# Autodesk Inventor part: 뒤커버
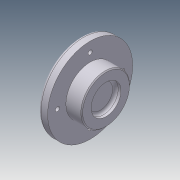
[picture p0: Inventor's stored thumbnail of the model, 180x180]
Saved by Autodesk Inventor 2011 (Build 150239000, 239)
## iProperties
Company: 한국ATC센터
Created: 2014-11
Part Number: 뒤커버
Document SubType Name: Modeling
Designer: KYOUNG IL JANG
Density: 2.71 g/cm^3
Material: 알루미늄-6061
Mass: 280.898 g
Surface Area: 198.677 cm^2
Volume: 103.653 cm^3
Author: KYOUNG IL JANG
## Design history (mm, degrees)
sketch "스케치1"
  geometry: L1 (-13.5, 0)-(13.5, 0); L2 (-13.5, 0)-(-13.5, 45.5); L3 (-13.5, 45.5)-(-3.5, 45.5); L4 (-3.5, 45.5)-(-3.5, 26); L5 (-3.5, 26)-(13.5, 26); L6 (13.5, 26)-(13.5, 0); 2 further points
  constraints: 12 end point, 3 parallel, 2 perpendicular, 1 coincident, 1 horizontal, 1 midpoint
  dimensions: "d0" = 27 distance of L1.start L1.end; "d1" = 91 diameter of L3 L1; "d2" = 52 diameter of L5 L1; "d3" = 10 distance of L2.end L3.end
revolve "회전1" sketch "스케치1" stored, may be unused: angle "d4" = 90 deg
sketch "스케치2"
  geometry: 2 further points
  constraints: 1 vertical alignment
  dimensions: "d14" = 35 distance of point (0, 0) point (0, 35)
hole "구멍2" sketch "스케치2" at (0, 35) diameter "d15" = 4.5; stored, may be unused: countersink angle "d19" = 90 deg, drill point angle "d21" = 118 deg; dims "d16" = 6, "d17" = 8, "d18" = 4.4, "d20" = 8
fillet "모깎기1" dims "d29" = 3
chamfer "모따기2" distance "d30" = 1; stored, may be unused: second distance "d31" = 2, angle "d32" = 30 deg
sketch "스케치3"
  geometry: L1 (-22.444, 6.652)-(-10, 14.967); L2 (-22.444, -6.652)-(-10, -14.967); L3 (10, -14.967)-(22.444, -6.652); L4 (22.444, 6.652)-(10, 14.967); A1 r 18 centre (0, 0) between (-18, 0) and (18, 0); A2 r 8 centre (18, 0) between (22.444, -6.652) and (22.444, 6.652); A3 r 8 centre (-18, 0) between (-22.444, 6.652) and (-22.444, -6.652); 1 further point
  constraints: 10 point on circle, 8 end point, 6 tangent, 3 centre point, 2 horizontal alignment, 2 parallel, 1 coincident, 1 equal radius
  dimensions: "d36" = 36 diameter of A1; "d37" = 16 diameter of A2
extrude "돌출1" join sketch "스케치3" distance "d38" = 7; taper "d39" = 0 deg
hole "구멍3" diameter "d43" = 32; stored, may be unused: countersink angle "d47" = 90 deg, drill point angle "d49" = 0 deg; dims "d41" = 10, "d42" = 10, "d44" = 6, "d45" = 4, "d46" = 2, "d48" = 6
fillet "모깎기2" dims "d40" = 3
node "솔리드1"
pattern_circular "원형 패턴2" dims angle "d34" = 360 deg
